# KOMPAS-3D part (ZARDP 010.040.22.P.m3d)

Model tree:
1. Плоскость XY
2. Плоскость ZX
3. Плоскость ZY
4. Ось X
5. Ось Y
6. Ось Z
7. Начало координат
8. Смещенная плоскость:2
     Расстояние = 77.5
9. Булева операция:1
10. Булева операция:3
11. Булева операция:5
12. Булева операция:6
